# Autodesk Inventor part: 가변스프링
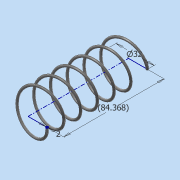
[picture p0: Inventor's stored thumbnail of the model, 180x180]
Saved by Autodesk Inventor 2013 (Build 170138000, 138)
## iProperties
Created: 2016-11
Part Number: 가변스프링
Material: 강철, 탄소
Document SubType Name: Modeling
Designer: dgall
Density: 1 g/cm^3
Mass: -0.00961573 g
Surface Area: 38.0291 cm^2
Volume: -0.00961573 cm^3
Author: dgall
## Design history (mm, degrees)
sketch "스케치1"
  geometry: L1 (16, 0)-(0, 0); L2 (0, 0)-(0, 84.368); L3 (0, 84.368)-(16, 84.368); C1 r 1 at (16, 0)
  constraints: 6 end point, 1 centre point, 1 coincident, 1 horizontal, 1 parallel, 1 perpendicular, 1 vertical alignment
  dimensions: "d0" = 2 diameter of C1; "d1" = 32 diameter of L3.end L2; "d2" = 84.36759 distance from line of L3 L1.start (derived)
feature "코일1" sketch "스케치1" pitch "d3" = 10; turns "d5" = 6; dims "d4" = 84.36759 (= d2), "d6" = 0, angle "d7" = 90 deg, angle "d8" = 90 deg, "d9" = 0, "d10" = 0
node "작업 평면1"
feature "분할1"
feature "분할2"
node "솔리드1"
